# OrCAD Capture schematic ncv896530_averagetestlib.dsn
size A
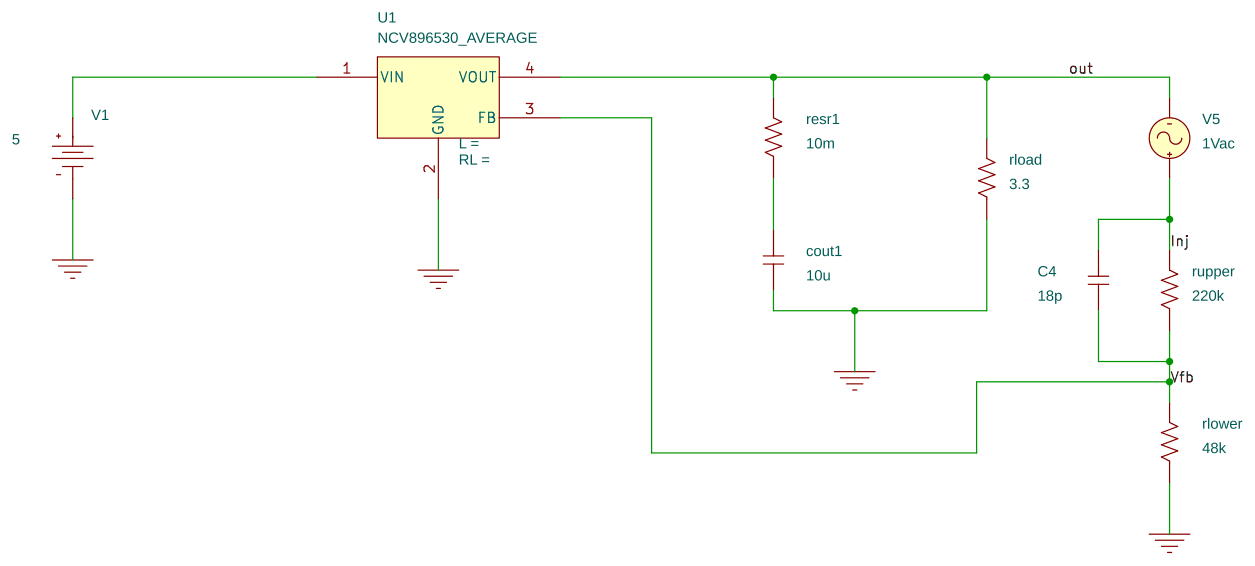
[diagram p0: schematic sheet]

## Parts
C4  18p  [RAD/CK05]
cout1  10u  [RAD/CK05]
resr1  10m  [AX/RC05]
rload  3.3  [AX/RC05]
rlower  48k  [AX/RC05]
rupper  220k  [AX/RC05]
U1  NCV896530_AVERAGE
V1  VDC
V5  VAC

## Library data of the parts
C4 cout1 = C
resr1 rload rlower rupper = R
U1 = NCV896530_AVERAGE
V1 = VDC: DC: 5
V5 = VAC: ACMAG: 1Vac

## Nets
0: cout1.1 rload.1 rlower.1 U1.2(GND) V1.1(-)
Inj: C4.2 rupper.2 V5.1(+)
out: resr1.2 rload.2 U1.4(VOUT) V5.2(-)
Vfb: C4.1 rlower.2 rupper.1 U1.3(FB)
N178882: cout1.2 resr1.1
N178952: U1.1(VIN) V1.0(+)
